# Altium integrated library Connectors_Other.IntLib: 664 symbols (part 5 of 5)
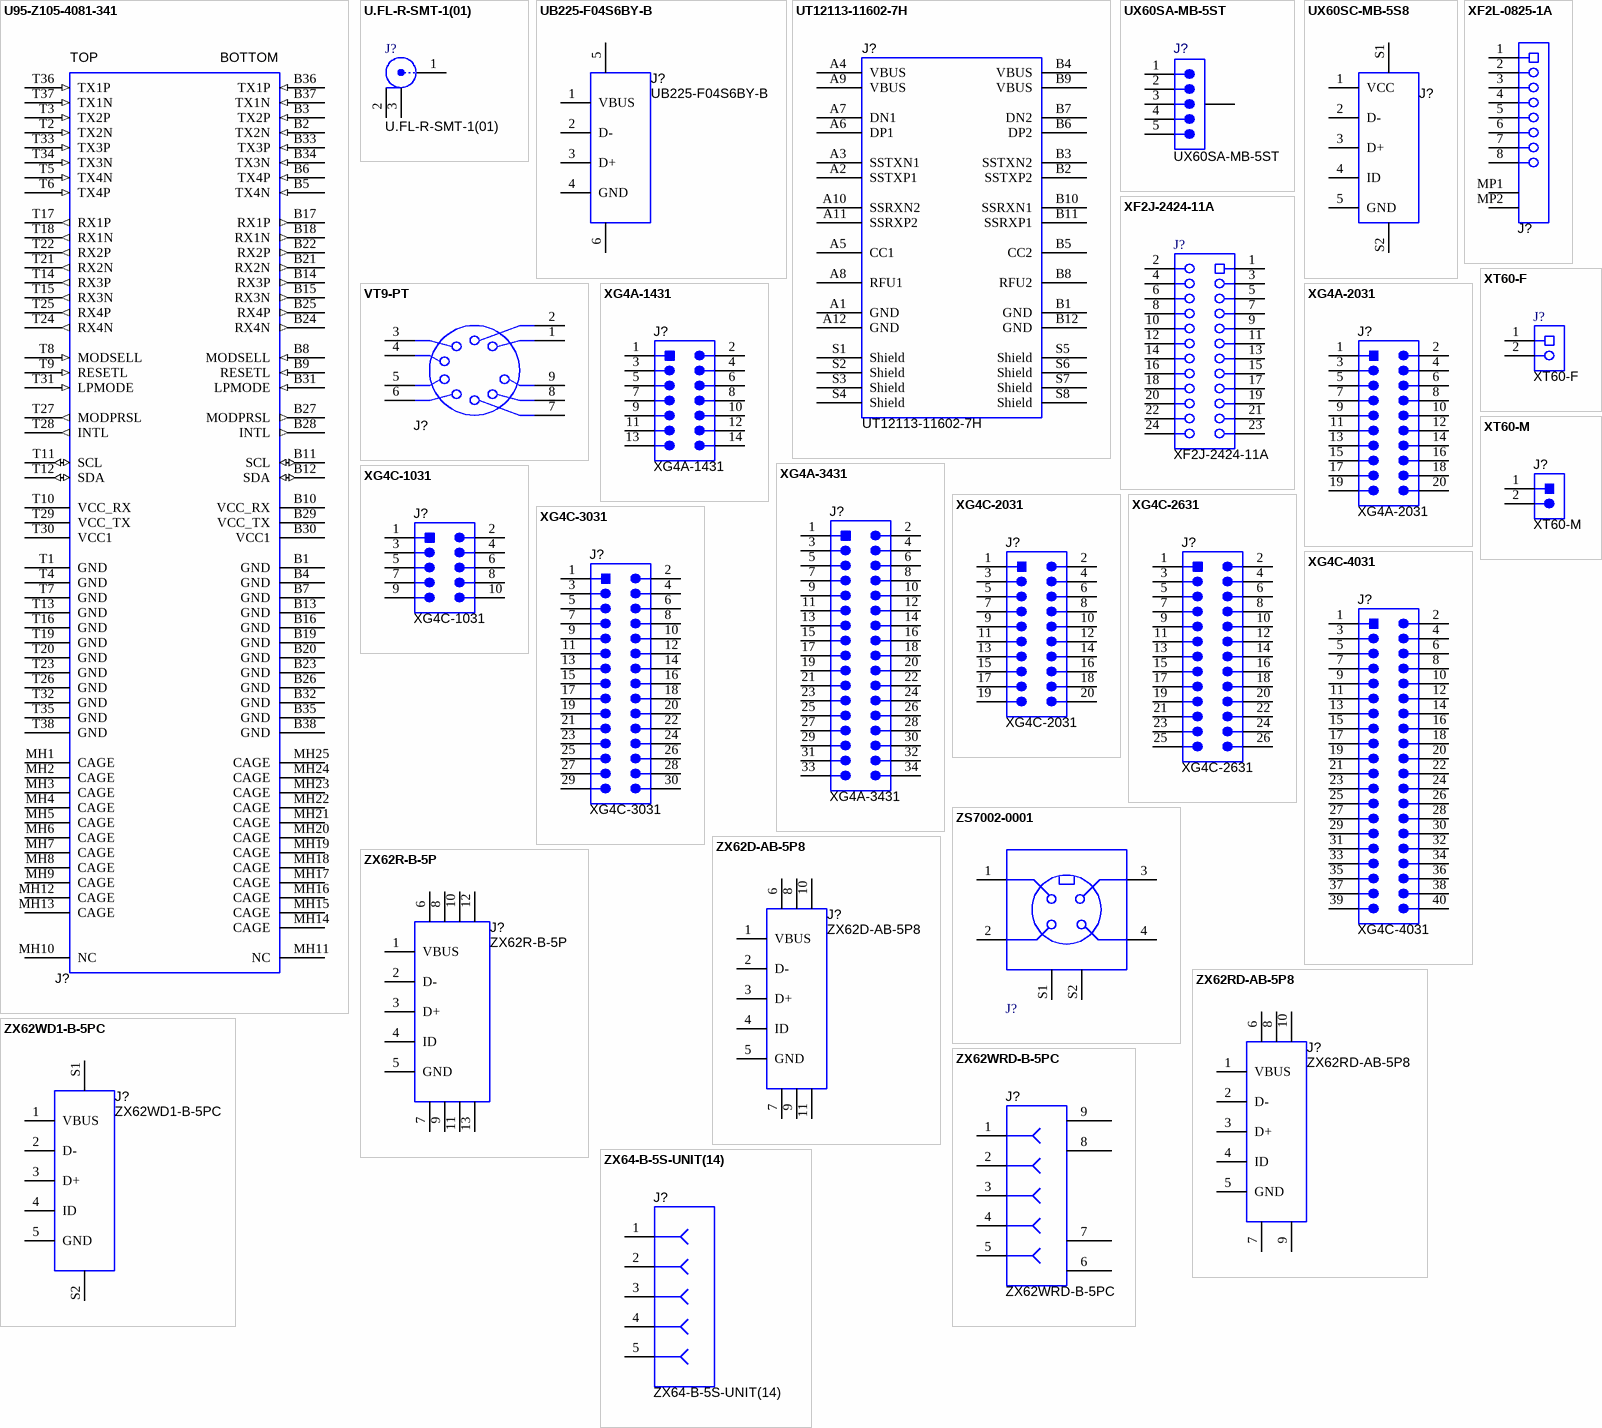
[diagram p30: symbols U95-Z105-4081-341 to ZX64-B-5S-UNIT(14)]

## XF2J-2424-11A
designator J?
FFC & FPC Connectors .5mm SlideLock 24Pin ZIF Single Adhesive, SMT; Manufacturer: Omron Electronic Components; SymbolCreator: a0799628; CompType: FFC or FPC
footprint OMRON_XF2J-2424-11A
pins: 1, 2, 3, 4, 5, 6, 7, 8, 9, 10, 11, 12, 13, 14, 15, 16, 17, 18, 19, 20, 21, 22, 23, 24

## XF2L-0825-1A
designator J?  (value not drawn)
Connector, Receptacle, FPC, 0.5mm, R/A, SMT; Manufacturer: Omron Electronic Components; SymbolCreator: Altium; CompType: FFC or FPC; Pitch_mm: 0.5; Gender: Female; Row_Count: 1; ContactFinish: Gold
footprint Omron_XF2L-0825-1A
pins: 1, 2, 3, 4, 5, 6, 7, 8, MP1, MP2

## XG4A-1431
designator J?
Connector, 7x2, 3A 300V STRT DIP, TH; Manufacturer: Omron Electronic Components; SymbolCreator: a0412235
footprint CONN_XG4A-1431
pins: 1, 2, 3, 4, 5, 6, 7, 8, 9, 10, 11, 12, 13, 14

## XG4A-2031
designator J?
Header(shrouded), 2.54mm, 10x2, Gold, TH; Manufacturer: Omron Electronic Components; SymbolCreator: a0412235; Pitch_mm: 2.54; Gender: Male; Shrouded: Y; Row_Count: 2; Current_A: 3; Voltage_V: 300
footprint Omron_XG4A-2031
pins: 1, 2, 3, 4, 5, 6, 7, 8, 9, 10, 11, 12, 13, 14, 15, 16, 17, 18, 19, 20

## XG4A-3431
designator J?
Connector, 17x2, 3A 300V STRT DIP, TH; Manufacturer: Omron Electronic Components; SymbolCreator: a0411947
footprint CONN_XG4A-3431
pins: 1, 2, 3, 4, 5, 6, 7, 8, 9, 10, 11, 12, 13, 14, 15, 16, 17, 18, 19, 20, 21, 22, 23, 24, 25, 26, 27, 28, 29, 30, 31, 32, 33, 34

## XG4C-1031
designator J?
Header (shrouded), 100mil, 5x2, Gold, TH; Manufacturer: Omron Electronic Components; SymbolCreator: a0412235; Green_Lifecycle: Not Set; Green_REACh: Incomplete
footprint OMRON_XG4C-1031
pins: 1, 2, 3, 4, 5, 6, 7, 8, 9, 10

## XG4C-2031
designator J?
Header(shrouded), 2.54mm, 10x2, Gold, TH; Manufacturer: Omron Electronic Components; SymbolCreator: a0412235; Pitch_mm: 2.54; Gender: Male; Shrouded: Y; Row_Count: 2; Current_A: 3; Voltage_V: 300
footprint Omron_XG4C-2031
pins: 1, 2, 3, 4, 5, 6, 7, 8, 9, 10, 11, 12, 13, 14, 15, 16, 17, 18, 19, 20

## XG4C-2631
designator J?
Header(shrouded), 2.54mm, 13x2, Gold, TH; Manufacturer: Omron Electronic Components; SymbolCreator: a0412235; Pitch_mm: 2.54; Gender: Male; Shrouded: Y; Row_Count: 2; Current_A: 3; Voltage_V: 300
footprint Omron_XG4C-2631
pins: 1, 2, 3, 4, 5, 6, 7, 8, 9, 10, 11, 12, 13, 14, 15, 16, 17, 18, 19, 20, 21, 22, 23, 24, 25, 26

## XG4C-3031
designator J?
Connector, 15x2, 3A 300V STRT DIP, TH; Manufacturer: Omron Electronic Components; SymbolCreator: a0412235; Green_Lifecycle: Not Set; Green_REACh: Incomplete
footprint OMRON_XG4C-3031
pins: 1, 2, 3, 4, 5, 6, 7, 8, 9, 10, 11, 12, 13, 14, 15, 16, 17, 18, 19, 20, 21, 22, 23, 24, 25, 26, 27, 28, 29, 30

## XG4C-4031
designator J?
Header(shrouded), 2.54mm, 20x2, Gold, TH; Manufacturer: Omron Electronic Components; SymbolCreator: a0412235; Pitch_mm: 2.54; Gender: Male; Shrouded: Y; Row_Count: 2; Current_A: 3; Voltage_V: 300
footprint Omron_XG4C-4031
pins: 1, 2, 3, 4, 5, 6, 7, 8, 9, 10, 11, 12, 13, 14, 15, 16, 17, 18, 19, 20, 21, 22, 23, 24, 25, 26, 27, 28, 29, 30, 31, 32, 33, 34, 35, 36, 37, 38, 39, 40

## XT60-F
designator J?
XT60 Connector, Female, Gold, TH; Manufacturer: heXTronik; SymbolCreator: a0412235; CompType: Receptacle; Pitch_mm: 7.6; Row_Count: 1
footprint Hextronik_XT60-F
pins: 1, 2

## XT60-M
designator J?
XT60 Connector, Male, Gold, TH; Manufacturer: heXTronik; SymbolCreator: a0412235; CompType: Header; Pitch_mm: 7.6; Shrouded: Y; Row_Count: 1
footprint Hextronik_XT60-M
pins: 1, 2
1 alternate drawing of the same symbol

## ZS7002-0001
designator J?  (value not drawn)
EtherCAT P, 4 Pos, TH; Manufacturer: Beckhoff; SymbolCreator: Altium; CompType: Socket; Gender: Female; Current_A: 3; Voltage_V: 30
footprint Beckhoff_ZS7002-0001
pins: 1, 2  , 3, 4  , S1, S2

## ZX62D-AB-5P8
designator J?
Connector, Receptacle, Micro-USB Type AB, R/A, Bottom Mount SMT; Manufacturer: Hirose Electric Co. Ltd.; SymbolCreator: a0411947; CompType: USB; Gender: Female; Green_Lifecycle: Not Set; Green_REACh: Incomplete
footprint Hirose-ZX62D-AB-5P8
pins: 1 VBUS, 2 D-, 3 D+, 4 ID, 5 GND, 6, 7, 8, 9, 10, 11

## ZX62R-B-5P
designator J?
Connector, Receptacle, Micro-USB Type B, SMT; Manufacturer: Hirose Electric Co. Ltd.; SymbolCreator: a0799628; CompType: USB; Gender: Female; Green_Lifecycle: Not Set; Green_REACh: Incomplete
footprint Hirose_ZX62R-B-5P
pins: 1 VBUS, 2 D-, 3 D+, 4 ID, 5 GND, 6, 7, 8, 9, 10, 11, 12, 13

## ZX62RD-AB-5P8
designator J?
Connector, Receptacle, Micro-USB Type AB, R/A, Bottom Mount SMT; Manufacturer: Hirose Electric Co. Ltd.; SymbolCreator: Altium; CompType: USB; Pitch_mm: 0.65; Gender: Female; Row_Count: 1
footprint Hirose_ZX62RD-AB-5P8
pins: 1 VBUS, 2 D-, 3 D+, 4 ID, 5 GND, 6, 7, 8, 9, 10

## ZX62WD1-B-5PC
designator J?
Connector, Receptacle, Micro-USB Type B, Splash-Proof, R/A, Bottom Mount SMT; Manufacturer: Hirose Electric Co. Ltd.; SymbolCreator: a0799628; CompType: USB; Gender: Female; Green_Lifecycle: Not Set; Green_REACh: Incomplete
footprint Hirose_ZX62WD1-B-5PC
pins: 1 VBUS, 2 D-, 3 D+, 4 ID, 5 GND, S1 6, S2 7

## ZX62WRD-B-5PC
designator J?
Connector, Receptacle, Micro-USB Type B, R/A, Top Mount SMT; Manufacturer: Hirose Electric Co. Ltd.; SymbolCreator: a0412235; CompType: USB; Gender: Female
footprint CONN_HIrose_ZX62WRD-B-5PC
pins: 1, 2, 3, 4, 5, 6, 7, 8, 9

## ZX64-B-5S-UNIT(14)
designator J?
Connector, Plug, Micro-USB Type B, R/A, Bottom Mount SMT; Manufacturer: Hirose Electric Co. Ltd.; SymbolCreator: a0412235; CompType: USB; Gender: Male; Note: Shielding plate required…ZX64-B-SLDC is in Hardware.IntLib
footprint CONN_ZX64-B-5S-UNIT14
pins: 1, 2, 3, 4, 5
